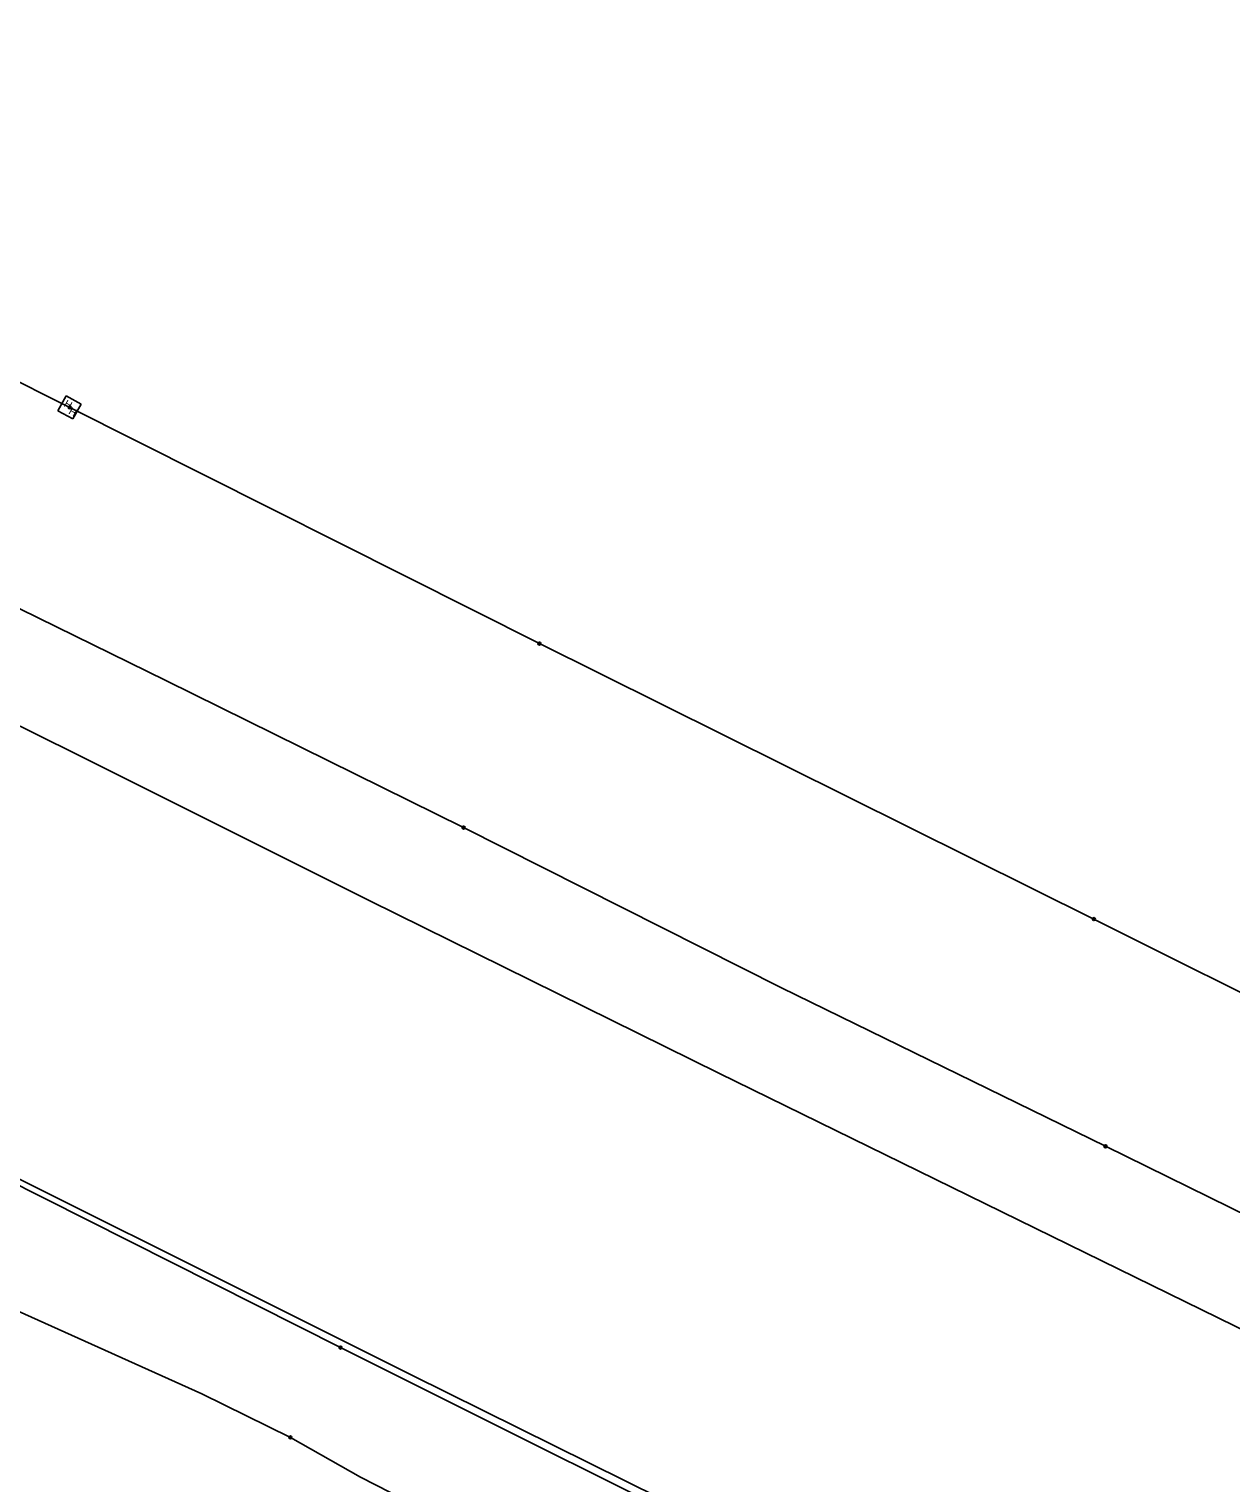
# Model space of a CAD drawing. Extents: x 2244485 to 2250986, y 199568 to 203007.
# Drawn here: x 2244898.9 to 2245302.1, y 202470.8 to 202958.5 of the extents above; entities that cross this region are included whole.
import ezdxf

# ---------------------------------------------------------------- set-up
doc = ezdxf.new("R2010")
doc.units = 0
for name, color, linetype in [('Default', 7, 'Continuous'), ('Exist Utilities Gas Meter CELL', 7, 'Continuous'), ('Exist Utilities Gas UG Line SUE LOS B', 7, 'Continuous'), ('Exist Utilities Telephone UG Cable SUE LOS C', 7, 'Continuous'), ('Exist Utilities Telephone UG FO SUE LOS B', 7, 'Continuous'), ('Exist Utilities Telephone UG FO SUE LOS C', 7, 'Continuous')]:
    doc.layers.add(name, color=color, linetype=linetype)

# ---------------------------------------------------------------- blocks, each defined once
blk = doc.blocks.new('SurveyPointCell')
at = {"layer": 'Default'}
for p, q in [((-0.5, 0), (0.5, 0)), ((0, -0.5), (0, 0.5))]:
    blk.add_line(p, q, dxfattribs=at)
blk.add_circle((0, 0), 0.5, dxfattribs=at)

msp = doc.modelspace()

# ---------------------------------------------------------------- linework, layer by layer
at = {"layer": 'Exist Utilities Gas Meter CELL'}
for p, q in [((2244911.34, 202835.48), (2244908.57, 202830.47)), ((2244916.35, 202832.71), (2244911.34, 202835.48)), ((2244908.57, 202830.47), (2244913.59, 202827.7)), ((2244912.46, 202831.59), (2244912.46, 202831.59)), ((2244913.59, 202827.7), (2244916.35, 202832.71))]:
    msp.add_line(p, q, dxfattribs=at)
at = {"layer": 'Exist Utilities Gas UG Line SUE LOS B'}
msp.add_lwpolyline([(2244658.96, 202958.49), (2244721.96, 202928.3), (2244863.47, 202856.19), (2244912.51, 202831.57), (2245070.07, 202752.33), (2245256.14, 202659.91), (2245331.4, 202622.29), (2245514.38, 202531.76), (2245606.53, 202488.05), (2245652.12, 202465.42), (2245827.69, 202375.08), (2246001.01, 202291.84), (2246162.3, 202211.17), (2246329.12, 202125.74), (2246513.99, 202036.93), (2246642.7, 201974.75), (2246734.96, 201930.33), (2246858.92, 201868.26), (2246999.42, 201799.12), (2247177.53, 201710.71), (2247331.7, 201633.3), (2247466.92, 201567.22), (2247602.4, 201501.88), (2247749.1, 201426.01)], dxfattribs=at)
at = {"layer": 'Exist Utilities Telephone UG Cable SUE LOS C'}
msp.add_lwpolyline([(2244616.99, 202864.57), (2244821.95, 202761.17), (2244823.87, 202761.98), (2244826.85, 202767.1), (2244844.94, 202797.37), (2244826.91, 202761.73), (2244826.73, 202760.14), (2244827.76, 202758.24), (2244914.59, 202715.31), (2245013.24, 202666.09), (2245130.24, 202608.24), (2245342.53, 202504.23)], dxfattribs=at)
at = {"layer": 'Exist Utilities Telephone UG FO SUE LOS B'}
for points in [[(2244629.01, 202898.49), (2244702.01, 202861.79), (2244776.88, 202824.58), (2244852.79, 202784.99), (2244944.72, 202739.99), (2245044.67, 202690.62), (2245151.29, 202636.88), (2245260.01, 202583.68), (2245475.72, 202477.57)], [(2244549.31, 202739.15), (2244609.86, 202709.11), (2244677.79, 202678.26), (2244760.05, 202637.59), (2244890.2, 202573.21), (2245003.36, 202516.16), (2245157.86, 202439), (2245297.18, 202369.62), (2245354.5, 202340.75)], [(2244534.64, 202709.84), (2244609.27, 202669.97), (2244785.74, 202581.01), (2244840.19, 202553.14), (2244956.88, 202500.62), (2244986.55, 202486.03), (2245010.04, 202472.71), (2245040, 202457.4), (2245084.78, 202430.15), (2245170.23, 202380.19), (2245207.23, 202360.21), (2245246.97, 202340.05), (2245286.61, 202320.72), (2245320.18, 202303.77), (2245344.49, 202291.92), (2245347.99, 202287.98)]]:
    msp.add_lwpolyline(points, dxfattribs=at)
at = {"layer": 'Exist Utilities Telephone UG FO SUE LOS C'}
msp.add_lwpolyline([(2244555.09, 202740.38), (2244612.45, 202712.07), (2244680.5, 202678.83), (2244750.01, 202644.92), (2244809.78, 202614.66), (2244896.14, 202572.42), (2244969.14, 202536), (2245027.26, 202506.94), (2245218.26, 202412.25), (2245428.66, 202309.78), (2245606.8, 202219.11), (2245703.35, 202173.01), (2245852.59, 202097.7), (2245983.22, 202033.13), (2246107.4, 201971.58), (2246219.73, 201915.39), (2246355.16, 201847.48), (2246395.74, 201823.66), (2246448.95, 201797.92), (2246548.24, 201751.03)], dxfattribs=at)

# ---------------------------------------------------------------- block references
at = {"layer": 'Default'}
for p in [(2244912.51, 202831.57), (2245070.07, 202752.33), (2245044.67, 202690.62), (2245256.14, 202659.91), (2245260.01, 202583.68), (2245003.36, 202516.16), (2244986.55, 202486.03)]:
    msp.add_blockref('SurveyPointCell', p, dxfattribs=at)

# ---------------------------------------------------------------- texts
at = {"layer": 'Exist Utilities Gas Meter CELL'}
for p in [(2244910.35, 202832.08), (2244911.9, 202829.56)]:
    msp.add_text('H', height=2.5, rotation=331.0771, dxfattribs=at).set_placement(p)

doc.saveas('drawing.dxf')
